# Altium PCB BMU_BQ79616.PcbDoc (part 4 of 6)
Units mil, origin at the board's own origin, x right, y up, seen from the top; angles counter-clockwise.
Board outline 7605 x 4005 mil, 4 copper layers (Top Layer, Layer 1, Layer 2, Bottom Layer), stack 37.446 mil thick; 709 components, 447 nets, 2028 pads, 1862 vias.
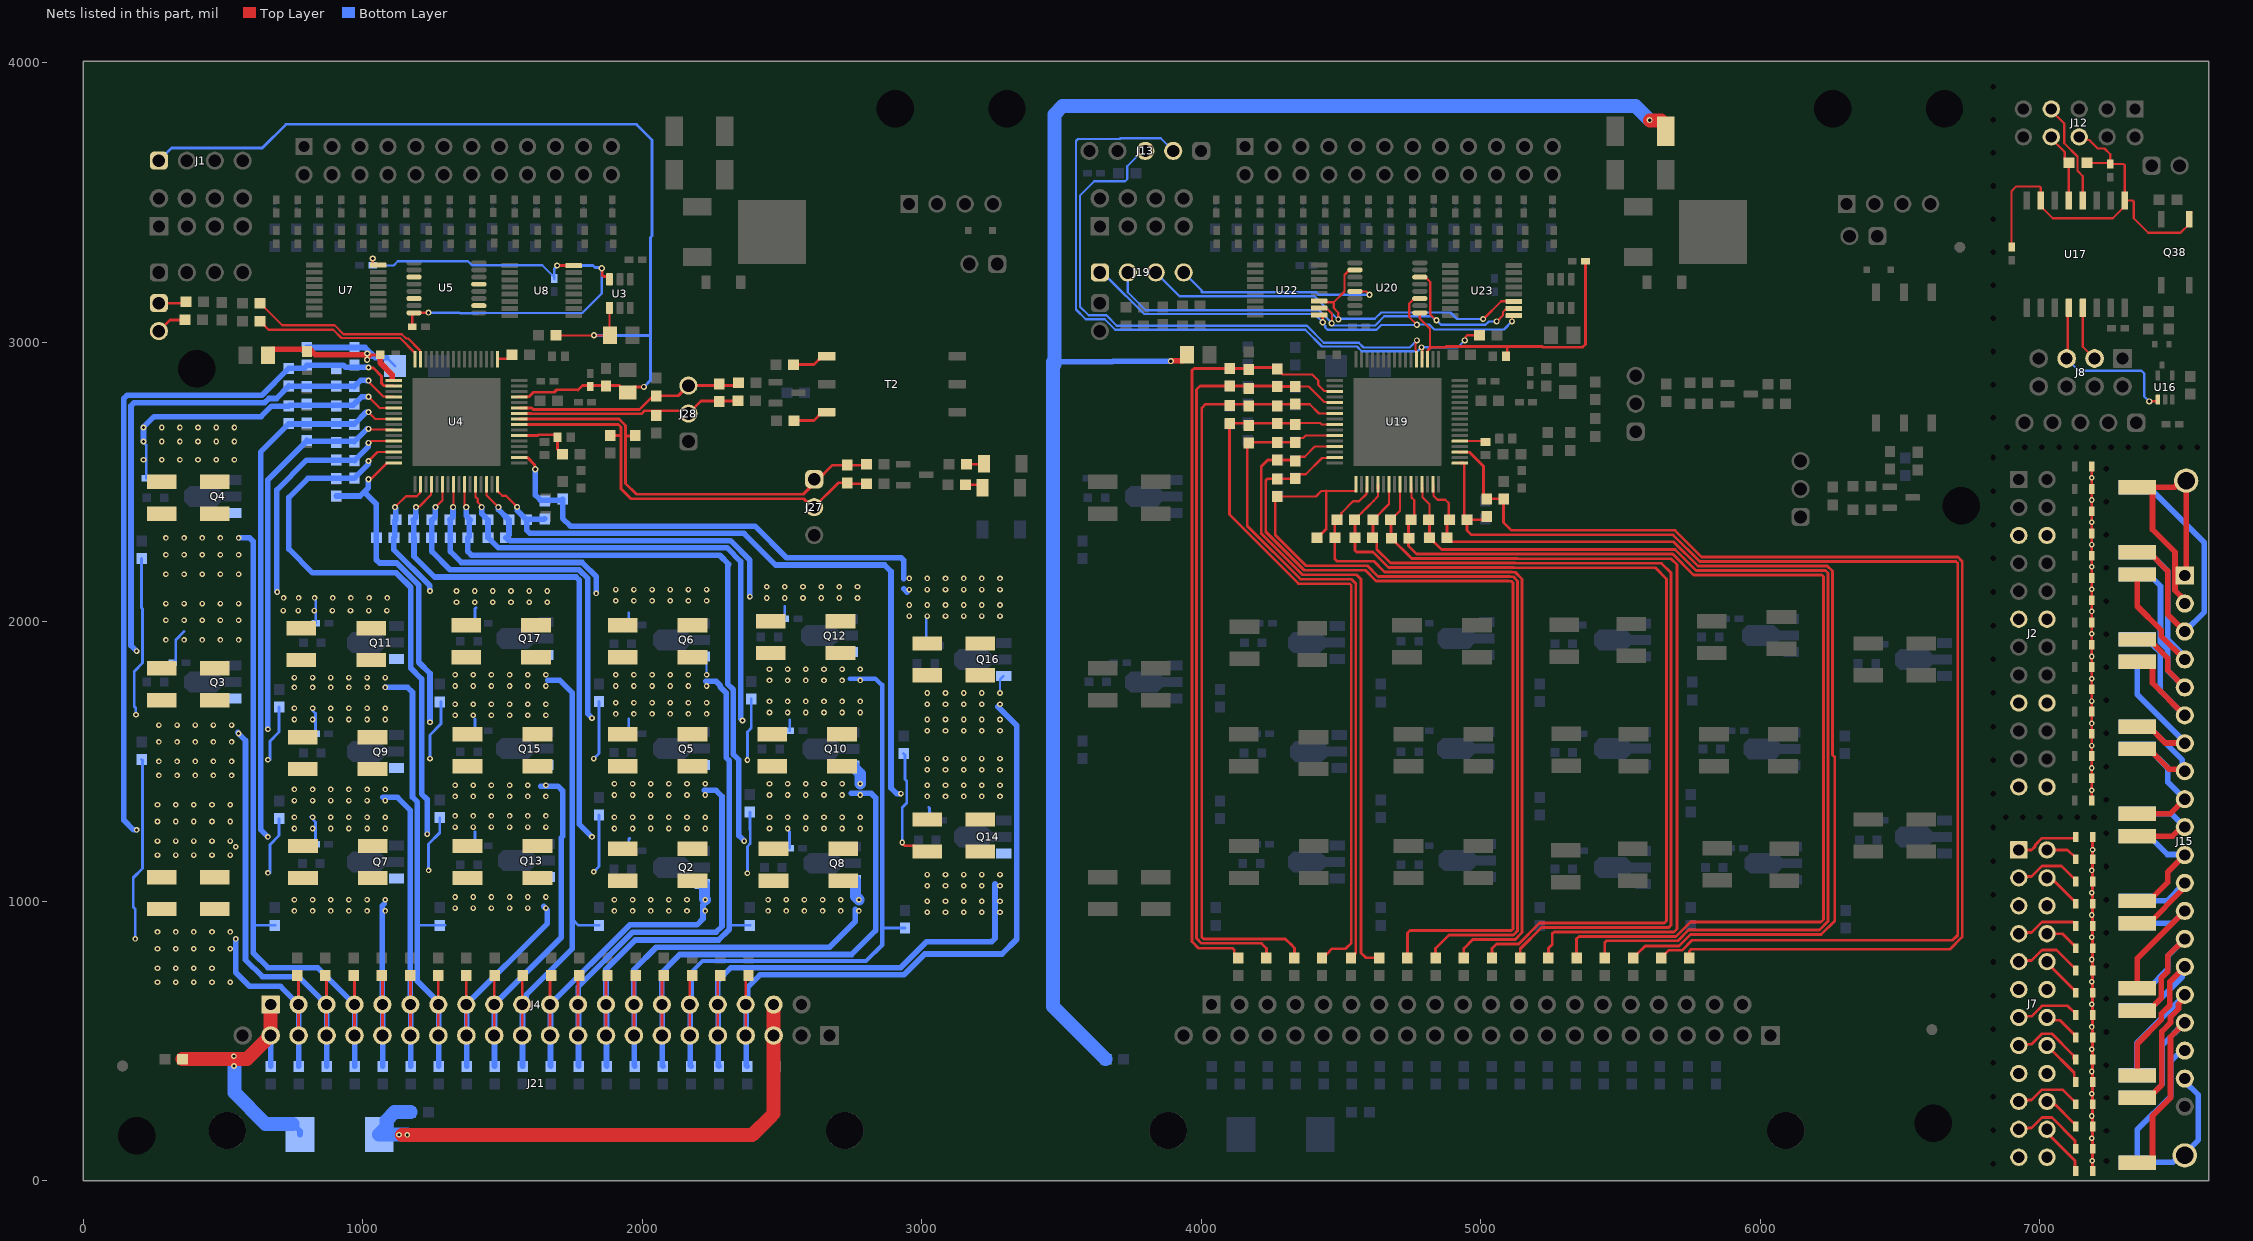
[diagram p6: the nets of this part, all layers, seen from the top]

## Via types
v1: diameter 20, hole 10, Top Layer to Bottom Layer, tented both sides, 1385 vias
v2: diameter 22.01, hole 12.01, Top Layer to Bottom Layer, tented both sides, 405 vias
v3: diameter 19.68, hole 7.87, Top Layer to Bottom Layer, 72 vias

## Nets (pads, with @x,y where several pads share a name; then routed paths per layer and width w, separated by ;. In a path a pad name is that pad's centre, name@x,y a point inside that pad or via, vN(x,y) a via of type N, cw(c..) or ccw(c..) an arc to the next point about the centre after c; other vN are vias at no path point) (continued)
A1_PWR: R152.2 R156.1 R417.1 | length 6223.9
  Top Layer w20: v2(3891.43,2932.62) 3891.97,2932.62 3892.85,2933.5 3935,2933.5 3950,2948.5 R156.1@3950,2955
  Top Layer w30: v2(5605,3795) v2@5606.85,3793.15 ; R152.2@5646.42,3793.15 5662.91,3776.65 R152.2@5662.91,3755 R152.2@5662.91,3745
  Top Layer w50: v2@5606.85,3793.15 R152.2@5646.42,3793.15
  Bottom Layer w20: 3470,2930 3475,2930 3681.63,2930 3684.26,2932.62 v2(3891.43,2932.62)
  Bottom Layer w30: R417.1@3658.39,435 R417.1@3659.37,435
  Bottom Layer w50: 3470,2930 3470,623.39 R417.1@3658.39,435 ; 3475,2920 3475,2930 3475,3815.71 3504.29,3845 5555,3845 v2(5605,3795)
A1_REFHP: C165.2 U19.37 | length 92.5
  Top Layer w8: U19.37@4926.18,2646.69 5014.29,2646.69 C165.2@5017.36,2643.62
A1_RHS_T_MUX: J19.4 U20.13 | length 758.8
  Top Layer w8: U20.13@4550.22,3182.2 4589.78,3182.2 4601.98,3170 v2(4602.36,3170)
  Bottom Layer w8: J19.4@3937.36,3250 4002.36,3185 4002.36,3179 4411.7,3179 4420.7,3170 v2(4602.36,3170)
A1_RX: J13.2 R143.2 U19.52 | length 2542.7
  Top Layer w8: U19.52@4790.35,2940 4792.26,2941.91 v2@4792.26,2973.9 ; v2(4943.42,3006.91) 4946.1,3009.59 4946.1,3018.94 4952.16,3025 R143.2@4995.87,3025
  Bottom Layer w8: 3710,3727.48 3559.06,3727.48 3551.9,3720.31 3551.9,3117.3 3586.72,3082.48 3654.96,3082.48 3692.44,3045 4372.48,3045 4432.73,2984.75 4557.82,2984.75 4575.01,2967.56 4774.07,2967.56 v2(4788.42,2981.91) 4918.42,2981.91 v2(4943.42,3006.91) ; 3710,3730 3855,3730 J13.2@3900,3685
A1_RX_CO: J8.3 U17.13 | length 199.1
  Top Layer w8: U17.13@7154.95,3123.57 7154.95,2984.26 J8.3@7197.24,2941.97
A1_THER_A0: J19.3 U20.10 U22.11 U23.11 | length 1653.4
  Top Layer w8: U22.11@4445.71,3148.23 4450.57,3143.37 4474.05,3143.37 ; v2(4490.9,3082.01) 4490.9,3106.16 4474.05,3123.01 4474.05,3143.37 ; U20.10@4546.22,3258.98 4530.44,3258.98 4512.66,3241.2 4512.66,3181.98 4474.05,3143.37 ; v2(5008.82,3083.5) 5010.57,3083.5 5073.68,3146.61 U23.11@5121.54,3146.61
  Bottom Layer w8: J19.3@3837.36,3250 3922.36,3165 4405.9,3165 4488.9,3082.01 v2(4490.9,3082.01) 4492.73,3083.84 4620.93,3083.84 4644.09,3107 4892.1,3107 4915.6,3083.5 v2(5008.82,3083.5)
A1_THER_A1: J19.2 U20.6 U22.10 U23.10 | length 1816.9
  Top Layer w8: U22.10@4445.71,3119.31 4447.24,3117.78 4452.36,3117.78 4467.76,3102.39 4467.76,3069.11 v2(4466.65,3068) ; U20.6@4782.5,3233.39 4802.28,3233.39 4820.06,3215.61 4820.06,3099.78 4841.08,3078.77 v2(4841.88,3078.77) ; v2(5057.36,3074.8) 5058.46,3074.8 5079.65,3095.98 5079.65,3107.29 5088.52,3116.17 5116.68,3116.17 U23.10@5121.54,3121.02
  Bottom Layer w8: J19.2@3737.36,3250 3737.36,3179.4 3801.76,3115 4421.28,3115 4466.65,3069.63 v2(4466.65,3068) ; v2@4464.95,3063.2 4467.76,3060.39 4622.76,3060.39 4655.36,3093 4823.85,3093 4838.08,3078.77 v2(4841.88,3078.77) 4858.14,3062.5 5017.52,3062.5 5029.82,3074.8 v2(5057.36,3074.8)
A1_THER_A2: J19.1 U20.3 U22.9 U23.9 | length 1775.9
  Top Layer w8: U22.9@4431.05,3092.19 4434.81,3092.19 v2(4434.81,3071.77) ; v2(4772.02,3063.01) 4744.94,3090.05 4744.94,3138.84 4762.72,3156.61 U20.3@4782.5,3156.61 ; v2(5112.36,3075) 5112.36,3090.57 5117.22,3095.43 U23.9@5121.54,3095.43
  Bottom Layer w8: J19.1@3637.36,3250 3643.99,3250 3667.4,3226.59 3670.37,3226.59 3795.96,3101 4405.58,3101 v2(4434.81,3071.77) 4434.81,3067.98 4443.75,3059.03 4443.75,3052.92 4451.67,3045 4627.32,3045 4644.59,3062.27 4771.29,3062.27 v2(4772.02,3063.01) ; v2(4772.02,3063.01) 4772.94,3063.91 4816.09,3063.91 4834,3046 5083.37,3046 v2(5112.36,3075)
A1_TSREF: C158.1 R195.1 U19.51 U20.1 | length 1081.7
  Top Layer w8: U20.1@4782.5,3105.43 4782.5,3084.94 4819,3048.45 4819,2981.93 4820.4,2980.53
  Top Layer w10: U19.51@4810.04,2940 4810.94,2940.91 4810.94,2971.07 4820.4,2980.53 ; 4819.02,2981.91 4873.83,2981.91 4876.62,2984.7 5095,2984.7 5220.61,2984.7 5222.81,2982.5 5365.16,2982.5 5374.86,2992.2 5374.86,3289.86 R195.1@5375,3290 ; C158.1@5090.98,2950 5095,2954.02 5095,2984.86
A1_TX: J13.3 U19.53 | length 2071.8
  Top Layer w8: U19.53@4770.67,2940 4768.76,2941.91 4768.76,2971.86 4767.42,2973.21 4767.42,2998.63 4772,3003.21 v2(4772,3007)
  Bottom Layer w8: J13.3@3800,3685 3790.16,3685 3735,3629.84 3735,3583.97 3727.33,3576.3 3617.39,3576.3 3565.9,3524.8 3565.9,3127.79 3597.21,3096.48 3660.76,3096.48 3698.24,3059 4378.28,3059 4438.53,2998.75 4563.62,2998.75 4580.81,2981.56 4746.56,2981.56 v2(4772,3007)
A1_TX_CO: J8.5 U16.1 U17.12 | length 627.1
  Top Layer w8: J8.5@7097.24,2941.97 7101.09,2945.82 7101.09,3119.72 U17.12@7104.95,3123.57 ; v2(7392.76,2788.65) 7419.94,2788.65 7423.82,2792.52 U16.1@7423.82,2795
  Bottom Layer w8: J8.5@7097.24,2941.97 7140.7,2898.5 7365.01,2898.5 7375,2888.52 7375,2806.41 v2(7392.76,2788.65)
A1_USB2ANY_3.3V: C4.2 C120.2 J12.6 Q38.1 R147.1 U17.1 U17.7 | length 1549.2
  Top Layer w8: C120.2@6900.24,3340.59 6900.24,3540.97 6917.24,3557.97 6999.95,3557.97 7004.95,3552.97 U17.7@7004.95,3507.43 7004.95,3486.76 7047.74,3443.97 7262.15,3443.97 7304.95,3486.76 U17.1@7304.95,3507.43 ; J12.6@7137.24,3733.97 7147.53,3723.67 7178.09,3723.67 7208.63,3693.13 7233.07,3693.13 7253.24,3672.97 C4.2@7253.24,3638.21 ; R147.1@7169.24,3641.97 7249.48,3641.97 C4.2@7253.24,3638.21 ; Q38.1@7543.76,3464.97 7535.95,3457.16 Q38.1@7535.95,3440.61 7535.95,3422.89 7505.02,3391.97 7389.24,3391.97 7337.24,3443.97 7337.24,3502.74 7332.55,3507.43 U17.1@7304.95,3507.43 ; C4.2@7253.24,3638.21 7300.26,3638.21 7304.95,3633.53 U17.1@7304.95,3507.43
A1_USB2ANY_RX_3.3: J12.8 R147.2 U17.5 | length 254.6
  Top Layer w8: J12.8@7037.24,3733.97 7090.56,3680.65 7090.56,3655.06 7104.95,3640.67 U17.5@7104.95,3507.43
A1_USB2ANY_TX_3.3: J12.7 U17.4 | length 375.3
  Top Layer w8: J12.7@7037.24,3833.97 7088.24,3782.97 7088.24,3712.5 7135.93,3664.81 7135.93,3613.62 7154.95,3594.61 U17.4@7154.95,3507.43
A1_VC0: C219.2 C222.1 R501.2 U19.35 | length 4431
  Top Layer w10: U19.35@4926.18,2607.32 4927.09,2606.42 4960.19,2606.42 5010.28,2556.33 5010.28,2452.09 C219.2@5018.86,2443.5 ; C219.2@5022.36,2440 5080.87,2440 C222.1@5082.36,2438.5 5082.36,2355 5110.36,2327 5695.36,2327 5790.71,2231.65 6689.21,2231.65 6708.13,2231.65 6723.36,2216.42 6723.36,2197.5 6723.36,871.57 6679.6,827.81 5753.22,827.81 5747.36,821.95 R501.2@5747.36,796.5
A1_VC1: C215.2 C219.1 R493.2 U19.33 | length 4562.9
  Top Layer w10: U19.33@4926.18,2567.95 4940.87,2567.95 4941.77,2567.05 C215.2@4941.77,2365 ; C219.1@5022.36,2377.01 5010.35,2365 C215.2@4951.77,2365 4951.77,2326.59 4967.36,2311 5688.73,2311 5784.09,2215.65 6701.5,2215.65 6707.36,2209.79 6707.36,878.2 6689.17,860 5756.92,860 5720.92,824 5672.94,824 5646.42,797.48 R493.2@5646.42,796.5
A1_VC2: C211.2 C215.1 R483.2 U19.31 | length 3697.1
  Top Layer w8: U19.31@4829.72,2491.18 4831.63,2489.28 4831.63,2450.53 4845.34,2436.82 4873.31,2436.82 4885.54,2424.59 4885.54,2368.24 C215.1@4888.78,2365
  Top Layer w10: C215.1@4888.78,2365 4879.76,2355.98 C211.2@4879.76,2300 4893.46,2286.3 5690.81,2286.3 5777.46,2199.65 6225.99,2199.65 6240.69,2199.65 6259.44,2180.9 6259.44,1523.23 6267.36,1515.3 6267.36,929.25 6218.77,880.66 5750.91,880.66 5710.24,840 5588.99,840 5560.17,811.18 5559.19,811.18 5557.36,809.36 5557.36,808.37 R483.2@5545.49,796.5
A1_VC3: C207.2 C211.1 R473.2 U19.29 | length 3806.5
  Top Layer w8: U19.29@4790.35,2491.18 U19.29@4792.26,2489.28 ; U19.29@4792.26,2479.28 4792.26,2445.1 4817.36,2420 4817.36,2369.09 C207.2@4813.27,2365
  Top Layer w10: C207.2@4813.27,2365 4816.77,2361.5 C211.1@4816.77,2300 4817.76,2300 4859.5,2258.25 5696.23,2258.25 5770.83,2183.65 6234.07,2183.65 6243.44,2174.27 6243.44,927.96 6212.15,896.66 5744.28,896.66 5705.62,858 5450.41,858 5444.55,852.14 R473.2@5444.55,796.5
A1_VC4: C203.2 C207.1 R463.2 U19.27 | length 3963.1
  Top Layer w8: C207.1@4750.28,2365 4762.36,2377.09 4762.36,2435 4752.89,2444.47 U19.27@4752.89,2479.28 ; U19.27@4750.98,2491.18 U19.27@4752.89,2489.28
  Top Layer w10: C207.1@4750.28,2365 4741.77,2356.5 4741.77,2270.59 4770.11,2242.25 5687.74,2242.25 5762.34,2167.65 6221.58,2167.65 6227.44,2161.79 6227.44,934.58 6218.65,925.8 5750.79,925.8 5698.99,874 5352.36,874 5343.61,865.25 R463.2@5343.61,796.5
A1_VC5: C198.2 C203.1 R453.2 U19.25 | length 3108.6
  Top Layer w8: C198.2@4679.25,2365 4711.61,2397.36 U19.25@4711.61,2481.18
  Top Layer w10: C198.2@4679.25,2365 4679.25,2300.47 4678.78,2300 4679.76,2300 4753.51,2226.25 5131.71,2226.25 5132.97,2225 5682.36,2225 5702.36,2205 5702.36,900 5692.36,890 5262.23,890 5256.38,884.14 5256.38,845.2 5242.67,831.5 R453.2@5242.67,796.5
A1_VC6: C196.2 C198.1 R443.2 U19.23 | length 3731.9
  Top Layer w8: C198.1@4615.28,2365 4616.26,2365 4672.24,2420.98 U19.23@4672.24,2481.18
  Top Layer w10: C198.1@4615.28,2365 4615.28,2302.01 C196.2@4613.27,2300 4614.35,2298.92 4615.33,2298.92 4627.95,2286.3 4627.95,2259.41 4677.11,2210.25 5125.08,2210.25 5126.34,2209 ; R443.2@5141.74,796.5 5141.74,829.87 5217.87,906 5673.36,906 5681.36,914 5681.36,1552.76 5681.36,2175.14 5647.5,2209 ; 5126.34,2209 5647.5,2209 ; 5126.34,2209 5647.5,2209
A1_VC7: C192.2 C196.1 R433.2 U19.21 | length 3353
  Top Layer w8: C192.2@4548.27,2365 4562.97,2379.7 4564.18,2379.7 4577.36,2392.88 4577.36,2393.11 4594.86,2410.61 4617.31,2433.06 4632.87,2448.62 U19.21@4632.87,2474.9
  Top Layer w10: C192.2@4548.27,2365 4550.28,2362.99 C196.1@4550.28,2300 4550.28,2255.86 4556.13,2250 4614.73,2250 4670.48,2194.25 5118.46,2194.25 5119.71,2193 5625.58,2193 5665.36,2153.21 5665.36,1546.13 5665.36,929.84 5657.52,922 5211.24,922 5136.24,847 5056.62,847 5040.8,831.18 R433.2@5040.8,796.5 ; U19.21@4632.87,2474.9 U19.21@4632.87,2491.18
A1_VC8: C192.1 C221.2 R423.2 U19.19 | length 2549.1
  Top Layer w8: C192.1@4485.28,2365 4486.26,2365 4500.96,2379.7 4500.96,2388.3 4543.66,2431 4565.12,2431 4591.6,2457.48 U19.19@4591.6,2479.28 ; U19.19@4591.6,2489.28 U19.19@4593.5,2491.18
  Top Layer w10: C192.1@4485.28,2365 4478.27,2357.99 C221.2@4478.27,2300 4478.27,2224.09 4486.11,2216.25 4618.48,2216.25 4656.48,2178.25 5111.83,2178.25 5113.08,2177 5123.76,2177 5148.36,2152.4 5148.36,887.6 5123.76,863 4971.68,863 4939.86,831.18 R423.2@4939.86,796.5
A1_VC9: C217.2 C221.1 R494.2 U19.17 | length 3176.4
  Top Layer w8: C217.2@4271.77,2448.5 4410.78,2448.5 4429.87,2467.6 4447.36,2467.6 4552.23,2467.6 4554.13,2469.51 U19.17@4554.13,2491.18
  Top Layer w10: C217.2@4271.77,2448.5 4265,2441.73 4265,2310.51 4375.26,2200.25 4594.74,2200.25 4632.74,2162.25 5105.2,2162.25 5106.46,2161 5117.13,2161 5132.36,2145.77 5132.36,894.23 5117.13,879 4886.74,879 4838.92,831.18 R494.2@4838.92,796.5 ; C221.1@4415.28,2300 4416.26,2300 4429.96,2313.7 4429.96,2314.69 4447.36,2332.09 4447.36,2467.6
A1_VC10: C213.2 C217.1 R484.2 U19.15 | length 3137.6
  Top Layer w8: C213.2@4336.77,2512.01 4336.77,2512.99 4351.47,2527.69 4374.32,2527.69 4432.36,2585.73 4475.46,2585.73 U19.15@4477.36,2587.64
  Top Layer w10: C213.2@4336.77,2511.5 C217.1@4271.77,2511.5 4236.86,2511.5 4231,2505.64 4231,2321.88 4368.63,2184.25 4588.11,2184.25 4626.11,2146.25 5098.58,2146.25 5099.83,2145 5110.5,2145 5116.36,2139.14 5116.36,900.86 5110.5,895 4747.36,895 4737.99,885.62 R484.2@4737.99,796.5
A1_VC11: C209.2 C213.1 R474.2 U19.13 | length 2370.7
  Top Layer w8: C213.1@4336.77,2575.98 4351.47,2590.69 4370.36,2590.69 4406.68,2627.01 U19.13@4462.36,2627.01
  Top Layer w10: C213.1@4336.77,2575.98 C213.1@4336.77,2575 4333.27,2578.5 C209.2@4271.77,2578.5 4238.07,2578.5 4215,2555.43 4215,2315.25 4362,2168.25 4556.25,2168.25 4572.36,2152.14 4572.36,815 4589.88,797.48 4637.05,797.48 R474.2@4637.05,796.5 ; U19.13@4462.36,2627.01 U19.13@4477.36,2627.01
A1_VC12: C205.2 C209.1 R10.2 R464.2 U19.11 | length 2448.9
  Top Layer w8: C205.2@4336.77,2642.01 4336.77,2642.99 4351.47,2657.69 4365.06,2657.69 4373.74,2666.38 U19.11@4477.36,2666.38
  Top Layer w10: C205.2@4336.77,2642.01 4271.77,2642.01 4171.77,2642.01 4166.77,2647.01 4165,2645.24 4165,2342.63 4355.37,2152.25 4536.88,2152.25 4553.36,2135.77 4553.36,814.73 4536.11,797.48 R464.2@4536.11,796.5
A1_VC13: C200.2 C205.1 R10.1 R11.2 R454.2 U19.9 | length 2667.5
  Top Layer w8: C205.1@4336.77,2705 4341.77,2710 4342.78,2711 4352.36,2711 4426.36,2711 4431.61,2705.75 U19.9@4477.36,2705.75
  Top Layer w10: C205.1@4352.36,2710 4341.77,2710 4336.77,2710 4271.77,2710 4166.77,2710 R11.2@4101.77,2710 4101.77,2383.23 4348.75,2136.25 4530.25,2136.25 4537.36,2129.14 4537.36,898.68 4537.36,850 4517.36,830 4468.68,830 4449.86,811.18 4448.88,811.18 4435.17,797.48 R454.2@4435.17,796.5
A1_VC14: C197.2 C200.1 R11.1 R79.2 R444.2 U19.7 | length 2782.2
  Top Layer w8: C197.2@4336.77,2778.5 4388.56,2778.5 4421.95,2745.12 U19.7@4477.36,2745.12
  Top Layer w10: C200.1@4271.77,2771.5 C200.1@4278.78,2778.5 ; R444.2@4334.24,796.5 4334.24,832.48 4320.54,846.18 4319.55,846.18 4300.73,865 4008.22,865 4002.36,870.86 4002.36,2765 4015.87,2778.5 4101.77,2778.5 4166.77,2778.5 C200.1@4278.78,2778.5 ; C197.2@4336.77,2778.5 C200.1@4278.78,2778.5
A1_VC15: C193.2 C197.1 R79.1 R84.2 R434.2 U19.5 | length 2786.9
  Top Layer w8: C197.1@4336.77,2841.5 4385.06,2841.5 4440.16,2786.39 4475.46,2786.39 U19.5@4477.36,2784.49
  Top Layer w10: R434.2@4233.3,796.5 4233.3,831.18 4215.48,849 4001.59,849 3983.36,867.23 3983.36,2831 3995.87,2843.5 R84.2@4101.77,2843.5 4270.28,2843.5 C193.2@4271.77,2842.01 4272.28,2841.5 C197.1@4336.77,2841.5
A1_VC16: C193.1 R84.1 R179.2 R424.2 U19.3 | length 2802.9
  Top Layer w8: C193.1@4271.77,2905 4271.77,2904.02 4286.47,2889.31 4287.46,2889.31 4291.77,2885 4397.36,2885 4418.87,2863.49 4418.87,2847.28 4440.39,2825.76 4475.46,2825.76 U19.3@4477.36,2823.86
  Top Layer w10: R424.2@4132.36,796.5 4118.66,810.2 4118.66,825.2 4112.36,831.5 3990.87,831.5 3967.36,855 3967.36,2900 3973.86,2906.5 R84.1@4101.77,2906.5 4163.86,2906.5 4167.36,2910 4266.77,2910 C193.1@4271.77,2905
A1M_CELL0S: J2.5 J2.6 J2.11 J2.12 J2.17 J2.18 J2.23 J2.24 J7.5 J7.6 J7.11 J7.12 J7.17 J7.18 J7.23 J7.24 J15.18 J15.19 R242.1 RT1.2 RT2.1 RT3.2 RT4.1 RT5.2 RT6.1 RT7.2 RT8.1 RT9.2 RT10.1 RT11.2 RT12.1 RT13.2 RT14.1 RT15.2 RT16.1 RT17.2 RT18.1 RT19.2 RT20.1 RT21.2 RT22.1 RT23.2 RT24.1 RT25.2 RT26.1 RT27.2 RT28.1 RT29.2 RT30.1 RT31.2 RT32.1 TP2.1 | length 3399.2
  Top Layer w10: RT16.1@7186.81,1360 RT15.2@7186.81,1439.67 RT14.1@7186.81,1519.33 RT13.2@7186.81,1599 RT12.1@7186.81,1678.67 RT11.2@7186.81,1758.33 RT10.1@7186.81,1838 RT9.2@7186.81,1917.67 RT8.1@7186.81,1997.33 RT7.2@7186.81,2077 RT6.1@7186.81,2156.67 RT5.2@7186.81,2236.33 RT4.1@7186.81,2316 RT3.2@7186.81,2395.67 RT2.1@7186.81,2475.33 RT1.2@7186.81,2555 ; RT32.1@7190,34.53 7189.5,35.04 7189.5,70.69 v1(7189,71.19) 7189.5,71.69 7189.5,113.7 RT31.2@7190,114.2 7190,151.19 RT30.1@7190,193.87 RT29.2@7190,273.53 RT28.1@7190,353.2 RT27.2@7190,432.87 RT26.1@7190,512.53 RT25.2@7190,592.2 RT24.1@7190,671.87 RT23.2@7190,751.53 RT22.1@7190,831.2 RT21.2@7190,910.87 RT20.1@7190,990.53 RT19.2@7190,1070.2 7190,1110.03 RT18.1@7190,1149.87 7190,1155 v1(7190,1184.04) ; RT18.1@7190,1150 v1(7190,1184.04) ; RT17.2@7190,1229.53 v1(7190,1184.04)
  Bottom Layer w20: J15.19@7520,365 7520,355 7568.48,306.52 7568.48,145.46 7520,96.98 TP2.1@7520,90 7501.87,90 7476.87,65 R242.1@7350,65 7350,182.14 7470,302.14 7470,429.28 7472.12,429.28 7507.83,465 J15.18@7520,465
  other v1: 7187.33,151.19 7187.33,231.19 7187.33,310.48 7187.33,390.48 7187.33,470.15 7187.33,550.15 7187.33,631.41 7187.33,711.41 7187.33,791.08 7187.33,871.08 7187.33,950.37 7187.33,1030.37 7187.33,1110.03 7187.33,1396.99 7187.33,1476.66 7187.33,1556.66 7187.33,1635.95 7187.33,1715.95 7187.33,1795.61 7187.33,1875.61 7187.33,1956.88 7187.33,2036.88 7187.33,2116.54 7187.33,2196.54 7187.33,2275.83 7187.33,2355.83 7187.33,2435.5 7187.33,2515.5
A1M_CELL1: J15.17 R240.1 R242.2 | length 958.1
  Top Layer w20: R240.1@7350,63.86 7391.34,63.86 7404.43,76.95 7404.43,231.89 7469.02,296.48 7469.02,514.02 J15.17@7520,565
  Bottom Layer w20: R242.2@7350,297.28 7391.34,297.28 7440,345.94 7440,485 J15.17@7520,565
A1M_CELL2: J15.16 R238.1 R240.2 | length 823.9
  Top Layer w20: R240.2@7350,296.14 7391.34,296.14 7438.02,342.82 7438.02,533.78 7469.02,564.78 7469.02,586.12 7497.43,614.53 7497.43,631.62 7520,654.19 J15.16@7520,665
  Bottom Layer w20: R238.1@7350,376.98 7347.57,379.41 7347.57,491.69 7520,664.12 J15.16@7520,665
A1M_CELL3: J15.15 R236.1 R238.2 | length 709.8
  Top Layer w20: R236.1@7350,376 7350,489.6 7435.43,575.03 7435.43,596.37 7466.43,627.37 7466.43,711.43 J15.15@7520,765
  Bottom Layer w20: R238.2@7350,609.26 7391.34,609.26 7511.4,729.32 7511.4,756.4 J15.15@7520,765
A1M_CELL4: J15.14 R234.1 R236.2 | length 622
  Top Layer w20: R236.2@7350,608.28 7391.34,608.28 7435.43,652.38 7435.43,724.27 7458.39,747.23 7458.39,803.39 J15.14@7520,865
  Bottom Layer w20: R234.1@7350,688.96 7391.34,688.96 7459.16,756.78 7459.16,804.16 J15.14@7520,865
A1M_CELL5: J15.13 R232.1 R234.2 | length 535.4
  Top Layer w20: R232.1@7350,688.14 7350,795 J15.13@7520,965
  Bottom Layer w20: R234.2@7350,921.24 7475.4,921.24 7519.15,965 J15.13@7520,965
A1M_CELL6: J15.12 R230.1 R232.2 | length 435.7
  Top Layer w20: R232.2@7350,920.43 7391.34,920.43 7512.35,1041.44 7512.35,1057.35 J15.12@7520,1065
  Bottom Layer w20: R230.1@7350,1000.94 7455.94,1000.94 J15.12@7520,1065
A1M_CELL7: J15.11 R226.1 R230.2 | length 457.6
  Top Layer w20: R226.1@7350,1000.29 7391.34,1000.29 7458.39,1067.34 7458.39,1103.39 J15.11@7520,1165
  Bottom Layer w20: R230.2@7350,1233.22 7391.34,1233.22 7457.52,1167.04 7517.96,1167.04 J15.11@7520,1165
A1M_CELL8: J15.10 R222.1 R226.2 | length 373.3
  Top Layer w20: R226.2@7350,1232.57 7476.76,1232.57 7509.19,1265 J15.10@7520,1265
  Bottom Layer w20: R222.1@7350,1312.92 7472.08,1312.92 J15.10@7520,1265
A1M_CELL9: J15.9 R219.1 R222.2 | length 466.6
  Top Layer w20: R219.1@7350,1312.43 7467.43,1312.43 J15.9@7520,1365
  Bottom Layer w20: R222.2@7350,1545.2 7391.34,1545.2 7459.16,1477.38 7459.16,1425.84 J15.9@7520,1365
A1M_CELL10: J15.8 R217.1 R219.2 | length 457.5
  Top Layer w20: R219.2@7350,1544.71 7391.34,1544.71 7463.41,1472.65 7512.35,1472.65 J15.8@7520,1465
  Bottom Layer w20: R217.1@7350,1624.9 7391.34,1624.9 7511.4,1504.84 7511.4,1473.6 J15.8@7520,1465
A1M_CELL11: J15.7 R215.1 R217.2 | length 557.3
  Top Layer w20: R215.1@7350,1624.57 7391.34,1624.57 7450.02,1565.89 7519.11,1565.89 J15.7@7520,1565
  Bottom Layer w20: R217.2@7350,1857.18 7350,1740.05 7520,1570.05 J15.7@7520,1565
A1M_CELL12: J15.6 R211.1 R215.2 | length 653
  Top Layer w20: R215.2@7350,1856.86 7391.34,1856.86 7404.43,1843.77 7404.43,1780.57 J15.6@7520,1665
  Bottom Layer w20: R211.1@7350,1936.88 7391.34,1936.88 7406.93,1921.29 7406.93,1915.4 7432.93,1889.4 7432.93,1752.07 J15.6@7520,1665
A1M_CELL13: J15.5 R207.1 R211.2 | length 765.1
  Top Layer w20: R207.1@7350,1936.72 7391.34,1936.72 7458.39,1869.66 7458.39,1826.61 J15.5@7520,1765
  Bottom Layer w20: R211.2@7350,2169.16 7391.34,2169.16 7433.16,2127.34 7433.16,1925.94 7459.16,1899.94 7459.16,1825.84 J15.5@7520,1765
A1M_CELL14: J15.4 R205.1 R207.2 | length 852.9
  Top Layer w20: R207.2@7350,2169 7350,2055.4 7435.43,1969.97 7435.43,1949.57 J15.4@7520,1865
  Bottom Layer w20: R205.1@7350,2248.86 7391.34,2248.86 7459.16,2181.03 7459.16,1936.7 7520,1875.87 J15.4@7520,1865
A1M_CELL15: J15.3 R203.1 R205.2 | length 1047.3
  Top Layer w20: R203.1@7350,2248.86 7391.34,2248.86 7458.39,2181.8 7458.39,2026.61 J15.3@7520,1965
  Bottom Layer w20: R205.2@7350,2481.14 7391.34,2481.14 7590,2282.48 7590,2035 J15.3@7520,1965
A1M_CELL16S: J15.1 J15.2 R203.2 TP1.1 | length 996.4
  Top Layer w20: R203.2@7350,2481.14 R203.2@7391.34,2481.14 ; J15.2@7520,2065 7520,2077.17 7485,2112.17 7485,2249.15 7404.43,2329.72 7404.43,2468.05 R203.2@7391.34,2481.14 ; J15.1@7520,2165 7525,2170 TP1.1@7525,2505 7506.87,2505 7483.01,2481.14 R203.2@7391.34,2481.14
A1N_NTC0_C: J7.1 RT17.1 | length 222.4
  Top Layer w10: J7.1@6926.02,1183.49 6971.92,1183.49 6984.9,1196.47 6984.9,1200.85 7009.45,1225.4 7122.67,1225.4 RT17.1@7126.81,1229.53
A1N_NTC1_C: J7.2 RT18.2 | length 118.3
  Top Layer w10: J7.2@7026.81,1183.49 7100.68,1183.49 7126.81,1157.37 RT18.2@7126.81,1149.87
A1N_NTC2_C: J7.3 RT19.1 | length 245.4
  Top Layer w10: J7.3@6926.02,1083.49 6930.4,1087.87 6971.92,1087.87 7009.45,1125.4 7079.11,1125.4 7126.81,1077.7 RT19.1@7126.81,1070.2
A1N_NTC3_C: J7.4 RT20.2 | length 144.8
  Top Layer w10: J7.4@7026.81,1083.49 7040.83,1083.49 7056.01,1068.3 7056.54,1068.3 7121.81,1003.03 7125,1003.03 7126.81,1001.23 RT20.2@7126.81,990.53
A1N_NTC4_C: J7.7 RT21.1 | length 228.6
  Top Layer w10: J7.7@6926.02,883.49 6930.4,887.87 6971.92,887.87 7009.45,925.4 7119.78,925.4 7126.81,918.37 RT21.1@7126.81,910.87
A1N_NTC5_C: J7.8 RT22.2 | length 126.1
  Top Layer w10: J7.8@7026.81,883.49 7082.02,883.49 7126.81,838.7 RT22.2@7126.81,831.2
A1N_NTC6_C: J7.9 RT23.1 | length 253.1
  Top Layer w10: J7.9@6926.02,783.49 6930.4,787.87 6971.92,787.87 7009.45,825.4 7060.44,825.4 7126.81,759.03 RT23.1@7126.81,751.53
A1N_NTC7_C: J7.10 RT24.2 | length 153
  Top Layer w10: J7.10@7026.81,783.49 7026.81,779.37 7126.81,679.37 RT24.2@7126.81,671.87
A1N_NTC8_C: J7.13 RT25.1 | length 236.3
  Top Layer w10: J7.13@6926.02,583.49 6930.4,587.87 6971.92,587.87 7009.45,625.4 7101.11,625.4 7126.81,599.7 RT25.1@7126.81,592.2
A1N_NTC9_C: J7.14 RT26.2 | length 133.8
  Top Layer w10: J7.14@7026.81,583.49 7036.17,574.13 7072.71,574.13 7126.81,520.03 RT26.2@7126.81,512.53
A1N_NTC10_C: J7.15 RT27.1 | length 262.3
  Top Layer w10: J7.15@6926.02,483.49 6930.4,487.87 6971.92,487.87 7009.45,525.4 7044.16,525.4 7121.81,447.75 7121.81,437.87 RT27.1@7126.81,432.87
A1N_NTC11_C: J7.16 RT28.2 | length 171.7
  Top Layer w10: J7.16@7026.81,483.49 7124.59,385.7 7124.59,355.41 RT28.2@7126.81,353.2
A1N_NTC12_C: J7.19 RT29.1 | length 244
  Top Layer w10: J7.19@6926.02,283.49 6930.4,287.87 6971.92,287.87 7009.45,325.4 7082.44,325.4 7126.81,281.03 RT29.1@7126.81,273.53
A1N_NTC13_C: J7.20 RT30.2 | length 143.4
  Top Layer w10: J7.20@7026.81,283.49 7040.83,283.49 7054.35,269.97 7058.2,269.97 7121.81,206.37 7125,206.37 7126.81,204.56 RT30.2@7126.81,193.87
A1N_NTC14_C: J7.21 RT31.1 | length 280.9
  Top Layer w10: J7.21@6926.02,183.49 6930.4,187.87 6971.92,187.87 7009.45,225.4 7044.16,225.4 7126.81,142.75 RT31.1@7126.81,114.2
A1N_NTC15_C: J7.22 RT32.2 | length 190.4
  Top Layer w10: J7.22@7026.81,183.49 7026.81,171.14 7126.81,71.14 RT32.2@7126.81,34.53
A2_AVDD: C19.2 R30.2 U4.38 | length 210.4
  Top Layer w10: U4.38@1558.82,2666.38 1625.84,2666.38 1628.85,2669.39 1686.99,2669.39 C19.2@1696.38,2660 1696.38,2616.14 1712.52,2600 R30.2@1713.5,2600
A2_BAT: C13.2 C14.1 D2.1 R14.1 R29.2 R408.1 U4.1 | length 965.1
  Top Layer w10: v2@1020,2945 1022,2945 1026,2949 1032,2955 C14.1@1062,2955 ; U4.1@1105,2864.13 1105.91,2863.23 U4.1@1110,2863.23
  Top Layer w20: R29.2@660,2960 675,2975 800,2975 810,2975 815.2,2969.8 821.69,2963.31 ; R408.1@800,2972.99 800,2972.01 803.5,2968.5 808.7,2963.31 821.69,2963.31 ; v2@1020,2955 1015.66,2955 830,2955 821.69,2963.31 ; C14.1@1062,2955 1062,2926.66 1105,2883.66 U4.1@1105,2869.02
  Bottom Layer w10: v2@1020,2945 1044.37,2945 1085,2945 1085.63,2944.37 D2.1@1115,2915
  Bottom Layer w20: R14.1@799.41,2981.5 C13.2@969.93,2981.5 1007.87,2981.5 1044.37,2945 1045,2944.37 D2.1@1085.63,2944.37
  other v2: 1015.17,2937.59 1015.66,2959.78
A2_BBN: R51.1 U4.63 | length 674.6
  Top Layer w8: R51.1@631.5,3140 632.48,3140 711.48,3061 898.8,3061 930.8,3029 1139.24,3029 1154.24,3014 1161.21,3014 1204.55,2970.65 1204.55,2941.91 U4.63@1206.46,2940
A2_BBN_CELL: J3.1 R50.1 | length 99.1
  Top Layer w8: J3.1@270,3140 362.01,3140 R50.1@367.01,3145
A2_BBP: R47.1 U4.64 | length 625
  Top Layer w8: R47.1@647.83,3059.65 662.48,3045 893.59,3045 923.59,3015 1133.44,3015 1182.92,2965.53 1184.87,2965.53 1186.77,2963.62 U4.64@1186.77,2940
  Top Layer w10: R47.1@631.5,3075 632.48,3075 R47.1@647.83,3059.65
A2_BBP_CELL: J3.2 R46.1 | length 145.4
  Top Layer w8: J3.2@242.9,3030 J3.2@267.9,3055
  Top Layer w10: J3.2@270,3040 310,3080 R46.1@363.5,3080
A2_CB0: C75.2 C79.1 R130.2 R131.2 R138.1 U4.34 | length 1823
  Top Layer w10: U4.34@1558.82,2587.64 1559.72,2586.73 1589.89,2586.73 1614.7,2561.92 1614.7,2547.87 v2(1616.99,2545.57)
  Bottom Layer w10: R138.1@3016.38,1915 v1@3016.38,2016.38
  Bottom Layer w15: R138.1@3016.38,1915 R138.1@3020.32,1915
  Bottom Layer w20: v2(1616.99,2545.57) 1616.99,2453.01 1635,2435 1650,2435 1711.5,2435 C79.1@1715,2438.5 1715,2370 1743,2342 2403,2342 2516,2229 2926,2229 2935,2220 2935,2153.3 ; 2935,2118.3 2947.05,2106.25
  other v1: 2955,2020 3020,2020 3085,2020 3150,2020 3215,2020 3280,2020 2955,2060 3020,2060 3085,2060 3150,2060 3215,2060 3280,2060 2955,2115 3020,2115 3085,2115 3150,2115 3215,2115 3280,2115 2955,2155 3020,2155 3085,2155 3150,2155 3215,2155 3280,2155
A2_CB1: C71.2 C75.1 R122.2 R127.2 R136.1 U4.32 | length 2510.3
  Top Layer w8: U4.32@1482.05,2491.18 1482.05,2467.56 1498.79,2450.82 1511.74,2450.82 v2(1551.99,2410.57)
  Bottom Layer w10: 3025,1335 3027.76,1332.24 R136.1@3027.76,1290
  Bottom Layer w20: v2(1551.99,2410.57) 1552.38,2410.19 1552.38,2397.54 1584.92,2365 C71.2@1585.91,2365 ; C75.1@1650,2368.5 1648.25,2366.75 1587.66,2366.75 C71.2@1585.91,2365 ; v1(2925.36,1385) 2910,1385 2890,1405 2890,2180 2867,2203 2477,2203 2364,2316 1597.62,2316 1585.91,2327.72 C71.2@1585.91,2365
  other v1: 3020,1375 3085,1375 3150,1375 3215,1375 3280,1375 3020,1415 3085,1415 3150,1415 3215,1415 3280,1415 3020,1470 3085,1470 3150,1470 3215,1470 3280,1470 3020,1510 3085,1510 3150,1510 3215,1510 3280,1510
A2_CB2: C67.2 C71.1 R118.2 R121.2 R134.1 U4.30 | length 1305.1
  Top Layer w8: U4.30@1442.68,2491.18 1442.68,2452.32 v2(1485,2410)
  Bottom Layer w10: R134.1@2510,2010 2510,2055
  Bottom Layer w20: v2(1485,2410) 1485.38,2409.62 1485.38,2401.54 1521.93,2365 C71.1@1522.91,2365 1522.91,2311.02 1511.89,2300 C67.2@1510.91,2300 ; C67.2@1520.59,2296.88 1520.59,2291.3 1526.17,2291.3 1527.47,2290 2315,2290 2385,2220 v1(2385,2090)
  other v1: 2445,2085 2510,2085 2575,2085 2640,2085 2705,2085 2770,2085 2445,2125 2510,2125 2575,2125 2640,2125 2705,2125 2770,2125
A2_CB3: C63.2 C67.1 R112.2 R117.2 R123.1 U4.28 | length 1745.8
  Top Layer w8: U4.28@1403.31,2491.18 1403.31,2446.49 1411.01,2438.79 1411.01,2427.78 1425,2413.79 v2(1425,2410)
  Bottom Layer w10: R123.1@2527.76,1610 2527.76,1648.62
  Bottom Layer w20: v2(1425,2410) 1425.38,2409.62 1425.38,2387.02 C63.2@1437.72,2374.69 ; C63.2@1447.4,2365 1447.66,2364.74 1447.66,2300.26 C67.1@1447.91,2300 1448.9,2300 1484.9,2264 2304.23,2264 2352,2216.23 2352,1653 v1(2358.5,1646.5)
  other v1: 2455,1675 2520,1675 2585,1675 2650,1675 2715,1675 2780,1675 2455,1715 2520,1715 2585,1715 2650,1715 2715,1715 2780,1715
A2_CB4: C59.2 C63.1 R104.2 R106.1 R109.2 U4.26 | length 2281.1
  Top Layer w8: U4.26@1363.94,2491.18 1363.94,2419.85 1370,2413.79 v2(1370,2410)
  Bottom Layer w10: R106.1@2526.38,1190 2526.38,1248.62
  Bottom Layer w20: v2(1370,2410) 1370.38,2409.62 1370.38,2379.03 1374.72,2374.69 1374.72,2373.7 1383.43,2365 C63.1@1384.41,2365 1380.16,2360.75 1380.16,2304.25 C59.2@1375.91,2300 1375.91,2251.3 1389.2,2238 2277,2238 2309.75,2205.25 2305,2200.5 2305,1777.55 2326,1756.55 2326,1524.86 2345.5,1505.36 2345.5,1234.5 v1(2365,1215)
  other v1: 2455,1260 2520,1260 2585,1260 2650,1260 2715,1260 2780,1260 2455,1300 2520,1300 2585,1300 2650,1300 2715,1300 2780,1300
A2_CB5: C58.2 C59.1 R20.1 R102.2 R103.2 U4.24 | length 909.9
  Top Layer w8: v2(1323,2410) 1323.78,2410.78 1323.78,2490.4 U4.24@1324.57,2491.18
  Bottom Layer w10: R20.1@1951.38,1988.15 1951.38,2031.38
  Bottom Layer w20: v2(1323,2410) 1322.62,2409.62 1322.62,2376.71 1320.59,2374.69 1320.59,2373.7 1311.89,2365 C58.2@1310.91,2365 1311.91,2364 1311.91,2301 C59.1@1312.91,2300 1312.91,2251.3 1352.21,2212 1784.82,2212 1835,2161.82 v1(1835,2101.25)
  other v1: 1905,2075 1970,2075 2035,2075 2100,2075 2165,2075 2230,2075 1905,2115 1970,2115 2035,2115 2100,2115 2165,2115 2230,2115
A2_CB6: C54.2 C58.1 R17.1 R96.2 R99.2 U4.22 | length 1413.9
  Top Layer w8: v2(1260,2410) 1285.2,2435.2 U4.22@1285.2,2491.18
  Bottom Layer w10: R17.1@1951.38,1598.77 1951.38,1651.38
  Bottom Layer w20: v2(1260,2410) 1259.62,2409.62 1259.62,2376.7 1257.6,2374.69 1257.6,2373.7 1248.9,2365 C58.1@1247.91,2365 1246.91,2364 1246.91,2301 C54.2@1245.91,2300 1245.91,2292.38 1246.98,2291.3 1246.98,2251.3 1312.28,2186 1774.05,2186 1805,2155.05 1805,1670 v1(1820,1655)
  other v1: 1905,1670 1970,1670 2035,1670 2100,1670 2165,1670 2230,1670 1905,1710 1970,1710 2035,1710 2100,1710 2165,1710 2230,1710
A2_CB7: C5.2 C54.1 R12.1 R23.2 R26.2 U4.20 | length 1908
  Top Layer w8: v2(1190,2410) 1192.68,2412.68 1202.68,2412.68 1243.92,2453.92 1243.92,2489.28 U4.20@1245.83,2491.18
  Bottom Layer w10: R12.1@1951.38,1173.77 1951.38,1221.38 1955,1225
  Bottom Layer w20: v2(1190,2410) 1189.62,2409.62 1189.62,2373.7 C5.2@1180.91,2365 1181.91,2364 1181.91,2301 C54.1@1182.91,2300 1182.91,2234.02 1256.93,2160 1763.28,2160 1775,2148.28 1775,1275 v1(1820,1230)
  other v1: 1900,1260 1965,1260 2030,1260 2095,1260 2160,1260 2225,1260 1900,1300 1965,1300 2030,1300 2095,1300 2160,1300 2225,1300
A2_CB8: C5.1 C78.2 R15.2 R19.2 R139.1 U4.18 | length 548.1
  Top Layer w8: v2@1115,2415 1115.42,2414.58 1119.58,2414.58 1154.1,2449.1 1193.13,2449.1 1204.55,2460.53 1204.55,2489.28 U4.18@1206.46,2491.18
  Bottom Layer w10: R139.1@1401.38,1995 1401.38,2046.38 1405,2050
  Bottom Layer w20: v2(1115,2410) 1115,2409.46 1117.91,2406.54 C5.1@1117.91,2365 1114.41,2361.5 1114.41,2303.5 C78.2@1110.91,2300 1110.91,2257.17 1239.15,2128.92 v1@1239.15,2115.85
  other v1: 1335,2070 1400,2070 1465,2070 1530,2070 1595,2070 1660,2070 1240,2110 1335,2110 1400,2110 1465,2110 1530,2110 1595,2110 1660,2110
A2_CB9: C74.2 C78.1 R125.2 R126.2 R137.1 U4.16 | length 1271.8
  Top Layer w8: v2(1020,2510) 1022.68,2512.68 1031.11,2512.68 1086.38,2567.95 U4.16@1110,2567.95
  Bottom Layer w10: R137.1@1401.38,1610 1401.38,1651.38
  Bottom Layer w20: C74.2@904.41,2450 990,2450 1004.81,2464.81 ; v2(1020,2510) 1019.62,2509.62 1019.62,2479.62 1004.81,2464.81 ; v1(1240,1640) 1240,1815 1200,1855 1200,2131.3 1121.3,2210 1059.63,2210 1047.91,2221.72 C78.1@1047.91,2300 1047.91,2421.7 1004.81,2464.81
  other v1: 1330,1665 1395,1665 1460,1665 1525,1665 1590,1665 1655,1665 1330,1705 1395,1705 1460,1705 1525,1705 1590,1705 1655,1705
A2_CB10: C70.2 C74.1 R119.2 R120.2 R135.1 U4.14 | length 2085.4
  Top Layer w8: v2(1020,2575) 1052.32,2607.32 U4.14@1110,2607.32
  Bottom Layer w10: R135.1@1401.38,1198.54 1401.38,1248.62
  Bottom Layer w20: v2(1020,2575) 1019.62,2574.62 1019.62,2564.1 970,2514.49 C70.2@970,2513.5 969.74,2513.25 904.67,2513.25 C74.1@904.41,2512.99 802.99,2512.99 735,2445 735,2260 820,2175 1119.53,2175 1171.25,2123.28 1171.25,1833.75 1210,1795 1210,1383.5 1228.5,1365 1230,1365 v1(1230,1240)
  other v1: 1330,1265 1395,1265 1460,1265 1525,1265 1590,1265 1655,1265 1330,1305 1395,1305 1460,1305 1525,1305 1590,1305 1655,1305
A2_CB11: C66.2 C70.1 R113.2 R116.2 R124.1 U4.12 | length 959.1
  Top Layer w8: v2(1020,2640) 1023.79,2640 1030.48,2646.69 U4.12@1110,2646.69
  Bottom Layer w10: v1@827.05,2086.25 827.05,2083.54 831.38,2079.21 R124.1@831.38,1995
  Bottom Layer w20: v1(693.5,2106.5) 692,2108 692,2472 798.5,2578.5 C66.2@904.41,2578.5 905.41,2577.5 969,2577.5 C70.1@970,2576.5 970,2577.48 1019.62,2627.1 1019.62,2639.62 v2(1020,2640)
  other v1: 715,2040 768.71,2040 825.76,2040 890.76,2040 955.76,2040 1020.76,2040 1085.76,2040 716.29,2085.35 770,2085.35 827.05,2085.35 892.05,2085.35 957.05,2085.35 1022.05,2085.35 1087.05,2085.35
A2_CB12: C62.2 C66.1 R5.2 R105.2 R107.1 R108.2 U4.10 | length 1515.8
  Top Layer w8: v2(1020,2690) 1022.03,2687.97 1108.09,2687.97 U4.10@1110,2686.06
  Bottom Layer w10: v1@820,1685 820,1682.29 830.16,1672.14 R107.1@830.16,1598.76
  Bottom Layer w20: v1(660,1615) 660,2508.11 799.41,2647.52 R5.2@799.41,2648.5 801.91,2646 966.91,2646 C62.2@969.41,2643.5 969.41,2644.49 1014.54,2689.62 1019.62,2689.62 v2(1020,2690)
  other v1: 755,1650 820,1650 885,1650 950,1650 1015,1650 1080,1650 755,1690 820,1690 885,1690 950,1690 1015,1690 1080,1690
A2_CB13: C55.2 C62.1 R1.2 R5.1 R95.1 R100.2 R101.2 U4.8 | length 2041
  Top Layer w8: v2(1020,2750) 1044.57,2725.43 U4.8@1110,2725.43
  Bottom Layer w10: v1@812.05,1301.25 830.16,1283.14 R95.1@830.16,1203.76
  Bottom Layer w20: v1(660,1230) 634,1256 634,2607.11 734.41,2707.52 R1.2@734.41,2708.5 735.41,2707.5 968.41,2707.5 C62.1@969.41,2706.5 969.41,2707.48 1011.54,2749.62 1019.62,2749.62 v2(1020,2750)
  other v1: 755,1260 820,1260 885,1260 950,1260 1015,1260 1080,1260 755,1300 820,1300 885,1300 950,1300 1015,1300 1080,1300
A2_CB14: C7.2 C55.1 R1.1 R6.2 R16.1 R28.2 R67.2 U4.6 | length 1143.9
  Top Layer w8: v2(1020,2805) 1060.2,2764.8 U4.6@1110,2764.8
  Bottom Layer w10: v1(215,2645) 215,2642.29 224.33,2632.97 R16.1@224.33,2513.75
  Bottom Layer w20: v1(215,2645) 215,2696.72 252.39,2734.11 635.56,2734.11 672.95,2771.5 R1.1@734.41,2771.5 737.91,2775 799.41,2775 904.41,2775 965.91,2775 C7.2@969.41,2778.5 969.41,2779.49 978.11,2788.19 979.09,2788.19 995.52,2804.62 1019.62,2804.62 v2(1020,2805)
  other v1: 215,2580 280,2580 345,2580 410,2580 475,2580 540,2580 280,2645 345,2645 410,2645 475,2645 540,2645 215,2695 280,2695 345,2695 410,2695 475,2695 540,2695
A2_CB15: C6.2 C7.1 R2.2 R6.1 R13.1 R22.2 R27.2 U4.4 | length 2024.4
  Top Layer w8: v2(1020,2863) 1022.68,2860.32 1022.68,2856.31 1072.91,2806.08 1108.09,2806.08 U4.4@1110,2804.17
  Bottom Layer w10: R13.1@319.33,1853.75 325,1859.43 328.94,1859.43 330.07,1860.57 330.07,1935.07 360,1965
  Bottom Layer w20: v1(190,1895) 170,1915 170,2772.28 181.72,2784 648.68,2784 663.68,2799 690.89,2799 734.41,2842.52 R2.2@734.41,2843.5 735.41,2842.5 799.41,2842.5 904.41,2842.5 968.41,2842.5 C7.1@969.41,2841.5 969.41,2842.48 978.11,2851.18 979.09,2851.18 992.53,2864.62 1013.11,2864.62 1014.35,2863.38 1019.62,2863.38 v2(1020,2863)
  other v1: 295,1935 360,1935 425,1935 490,1935 555,1935 295,2005 360,2005 425,2005 490,2005 555,2005 295,2065 360,2065 425,2065 490,2065 555,2065
A2_CB16: C6.1 C13.1 R2.1 R14.2 R18.2 R21.2 U4.2 | length 2630.8
  Top Layer w10: v2(1020,2910) 1022.3,2907.7 1037.3,2907.7 1066.51,2878.49 1066.51,2853.49 1075.55,2844.45 1109.09,2844.45 U4.2@1110,2843.54
  Bottom Layer w20: v1(190,1255) 179,1255 144,1290 144,2798.28 155.72,2810 637.91,2810 R2.1@734.41,2906.5 788.39,2906.5 799.41,2917.52 R14.2@799.41,2918.5 930,2918.5 938.5,2910 v2(1020,2910)
  other v1: 265,1165 330,1165 395,1165 460,1165 525,1165 545,1195 265,1215 330,1215 395,1215 460,1215 525,1215 265,1285 330,1285 395,1285 460,1285 525,1285 265,1345 330,1345 395,1345 460,1345 525,1345
A2_CELL0: C82.1 D44.2 J4.19 J21.3 R9.2 | length 2236
  Top Layer w20: 2460,230 2470,240
  Top Layer w50: 1140,163.41 v1(1158.64,163.41) 2393.41,163.41 2460,230 ; 2470,240 J21.3@2470,519.29 J4.19@2470,630
  Bottom Layer w20: J4.19@2470,630 2472.5,627.5 2472.5,411.36 C82.1@2475,408.86
  Bottom Layer w50: v1(1158.64,163.41) 1157.05,165 D44.2@1058.46,165 1084.65,191.18 1084.65,215.74 1113.94,245.03 R9.2@1171.14,245
  other v1: 1129.2,163.8
A2_CELL0S: C83.1 J4.18 J21.4 Q16.3 R130.1 R131.1 R225.1 | length 2456.6
  Top Layer w10: J21.4@2370,519.29 J4.18@2370,630 R225.1@2370,723.5
  Bottom Layer w8: v1(3280,1745) 3280,1793.07 Q16.3@3292.87,1805.94
  Bottom Layer w15: J21.4@2370,519.29 J21.4@2372.36,521.65
  Bottom Layer w20: C83.1@2374.72,408.86 2372.36,411.22 2372.36,521.65 2372.36,627.64 J4.18@2370,630 2377.48,637.48 2377.48,692.48 2421,736 2935.7,736 3010.7,811 3287.21,811 3340,863.79 3340,1628.3 3272.05,1696.25
  other v1: 3020,1610 3085,1610 3150,1610 3215,1610 3280,1610 3020,1650 3085,1650 3150,1650 3215,1650 3280,1650 3020,1705 3085,1705 3150,1705 3215,1705 3280,1705 3020,1745 3085,1745 3150,1745 3215,1745
A2_CELL1: C85.1 J4.17 J21.5 Q14.3 R122.1 R127.1 R209.1 R213.1 | length 2180.8
  Top Layer w10: J21.5@2270,519.29 J4.17@2270,630 R209.1@2270,724.44 ; v1(2930,1210) 2931.91,1208.09 2931.91,1203.1 2935,1203.1 2939.59,1198.5 2974.41,1198.5 R127.1@3000,1172.91
  Bottom Layer w10: v1(2930,1210) 2930,1335 2946.36,1351.36 2946.36,1429.38 2940,1435.74 2940,1523.5 R213.1@2935,1528.5
  Bottom Layer w20: C85.1@2274.44,408.86 2272.22,411.08 2272.22,627.78 J4.17@2270,630 2270,715 2317,762 2924.93,762 3017.93,855 3250.34,855 3262.05,866.72 3262.05,1061.25
  other v1: 3020,960 3085,960 3150,960 3215,960 3280,960 3020,1000 3085,1000 3150,1000 3215,1000 3280,1000 3020,1055 3085,1055 3150,1055 3215,1055 3280,1055 3020,1095 3085,1095 3150,1095 3215,1095 3280,1095
A2_CELL2: C86.1 J4.16 J21.6 Q12.3 R118.1 R121.1 R193.1 R197.1 | length 2412
  Top Layer w10: J21.6@2170,519.29 J4.16@2170,630 R193.1@2170,725.38
  Bottom Layer w10: 2858.5,910.38 2865.38,903.5 R197.1@2940,903.5
  Bottom Layer w15: J21.6@2170,519.29 2172.08,521.37 J21.6@2172.7,521.99 ; J4.16@2177.7,630 2177.7,747.7 2215.5,785.5 2800.5,785.5 2858.5,843.5 2858.5,910.38 2858.5,1775 2855,1775 2833.75,1796.25 2742.05,1796.25
  Bottom Layer w20: J4.16@2170,630 2172.08,627.92 2172.08,521.37 2172.08,410.94 C86.1@2174.17,408.86
  other v1: 2455,1790 2520,1790 2585,1790 2650,1790 2715,1790 2780,1790 2455,1830 2520,1830 2585,1830 2650,1830 2715,1830 2780,1830
A2_CELL3: C88.1 J4.15 J21.7 Q10.3 R112.1 R117.1 R176.1 R180.1 | length 2247.4
  Top Layer w10: J21.7@2070,519.29 J4.15@2070,630 R176.1@2070,726.32
  Bottom Layer w10: v1(2376,1505) 2376,1606 2390,1620 R180.1@2390,1723.5
  Bottom Layer w20: C88.1@2073.89,408.86 2071.94,410.8 2071.94,628.06 J4.15@2070,630 2070,745 2134,809 2749,809 2835,895 2835,1370 2818.75,1386.25 2747.05,1386.25
  Bottom Layer w40: Q10.3@2749.8,1485.94 2755.08,1485.94 2757.36,1483.66 2757.36,1478.39 2780,1455.75 v1(2780,1420)
  other v1: 2455,1380 2520,1380 2585,1380 2650,1380 2715,1380 2780,1380 2455,1420 2520,1420 2585,1420 2650,1420 2715,1420
A2_CELL4: C89.1 J4.14 J21.8 Q8.3 R104.1 R109.1 R160.1 R164.1 | length 1769.2
  Top Layer w10: J21.8@1970,519.29 J4.14@1970,630 R160.1@1970,727.25
  Bottom Layer w10: v1(2376,1100) 2376,1196 2386,1206 2386,1254.56 2385,1255.56 R164.1@2385,1318.5
  Bottom Layer w20: C89.1@1973.61,408.86 1971.81,410.66 1971.81,628.19 J4.14@1970,630 1970,755 2050,835 2670,835 2762.05,927.05 2762.05,971.25
  Bottom Layer w40: Q8.3@2754.8,1076.57 2760.08,1076.57 2762.36,1074.28 2762.36,1017.64 v1(2775,1005)
  other v1: 2450,965 2515,965 2580,965 2645,965 2710,965 2775,965 2450,1005 2515,1005 2580,1005 2645,1005 2710,1005
A2_CELL5: C90.1 J4.13 J21.9 Q6.3 R102.1 R103.1 R144.1 R148.1 | length 2149.5
  Top Layer w10: J21.9@1870,519.29 J4.13@1870,630 R144.1@1870,728.19
  Bottom Layer w8: Q6.3@2214.8,1875.94 2216.28,1875.94 2230,1862.23 v1(2230,1810)
  Bottom Layer w10: 2311,915 2312.5,913.5 R148.1@2385,913.5
  Bottom Layer w20: C90.1@1873.33,408.86 1871.67,410.52 1871.67,628.33 J4.13@1870,630 1870,756.46 1974.54,861 2272.77,861 2311,899.23 2311,915 2311,1503.09 2300,1514.09 2300,1745.78 2279,1766.78 2279,1771.78 2264.54,1786.25 2227.05,1786.25
  other v1: 1905,1770 1970,1770 2035,1770 2100,1770 2165,1770 2230,1770 1905,1810 1970,1810 2035,1810 2100,1810 2165,1810
A2_CELL6: C91.1 J4.12 J21.10 Q5.3 R96.1 R99.1 R128.1 R132.1 | length 1849.9
  Top Layer w10: J21.10@1770,519.29 J4.12@1770,630 R128.1@1770,729.13
  Bottom Layer w10: v1(1826,1510) 1845,1529 R132.1@1845,1715
  Bottom Layer w20: C91.1@1773.05,408.86 1771.53,410.39 1771.53,519.29 1771.53,628.47 J4.12@1770,630 1770,693.23 1965.77,889 2264,889 2285,910 2285,1375 2263.75,1396.25 2222.05,1396.25
  other v1: 1900,1380 1965,1380 2030,1380 2095,1380 2160,1380 2225,1380 1900,1420 1965,1420 2030,1420 2095,1420 2160,1420 2225,1420
A2_CELL7: C92.1 J4.11 J21.11 Q2.3 R23.1 R26.1 R110.1 R114.1 | length 1431.8
  Top Layer w10: J21.11@1670,519.29 J4.11@1670,630 R110.1@1670,730.07
  Bottom Layer w10: v1(1826,1105) 1845,1124 R114.1@1845,1308.5
  Bottom Layer w20: C92.1@1672.78,408.86 1671.39,410.25 1671.39,628.61 J4.11@1670,630 1955,915 2195,915 2217.05,937.05 2217.05,986.25
  Bottom Layer w40: Q2.3@2214.8,1061.57 2220.08,1061.57 2222.36,1059.28 2222.36,1007.64 v1(2225,1005)
  other v1: 1900,965 1965,965 2030,965 2095,965 2160,965 2225,965 1900,1005 1965,1005 2030,1005 2095,1005 2160,1005
A2_CELL8: C93.1 J4.10 J21.12 Q17.3 R15.1 R19.1 R93.1 R97.1 | length 1835
  Top Layer w10: J21.12@1570,519.29 J4.10@1570,630 R93.1@1570,731
  Bottom Layer w10: 1749,936 1771.5,913.5 R97.1@1845,913.5
  Bottom Layer w20: C93.1@1572.5,408.86 1571.25,410.11 1571.25,519.29 1571.25,628.75 J4.10@1570,630 1570,642.17 1584.18,656.35 1584.18,664.18 1749,829 1749,936 1749,1746 1703.75,1791.25 1662.05,1791.25
  other v1: 1330,1770 1395,1770 1460,1770 1525,1770 1590,1770 1655,1770 1330,1810 1395,1810 1460,1810 1525,1810 1590,1810 1655,1810
A2_CELL9: C94.1 J4.9 J21.13 Q15.3 R125.1 R126.1 R210.1 R214.1 | length 1607.2
  Top Layer w10: J21.13@1470,519.29 J4.9@1470,630 R210.1@1470,731.94
  Bottom Layer w10: v1(1240,1510) 1240,1595 1280,1635 R214.1@1280,1713.5
  Bottom Layer w20: C94.1@1472.22,408.86 1471.11,409.97 1471.11,519.29 1471.11,628.89 J4.9@1470,630 1710,870 1710,1226.72 1715,1231.72 1715,1395.22 1698.28,1411.94 1636.19,1411.94
  other v1: 1330,1375 1395,1375 1460,1375 1525,1375 1590,1375 1655,1375 1330,1415 1395,1415 1460,1415 1525,1415 1590,1415 1655,1415
A2_CELL10: C95.1 J4.8 J21.14 Q13.3 R119.1 R120.1 R194.1 R198.1 | length 1117.3
  Top Layer w10: J21.14@1370,519.29 J4.8@1370,630 R194.1@1370,732.88
  Bottom Layer w10: v1(1235,1110) 1235,1205 1275,1245 R198.1@1275,1298.5
  Bottom Layer w20: C95.1@1371.94,408.86 1370.97,409.83 1370.97,519.29 1370.97,629.03 J4.8@1370,630 1660,920 1660,968.3 1647.05,981.25
  other v1: 1330,975 1395,975 1460,975 1525,975 1590,975 1655,975 1330,1015 1395,1015 1460,1015 1525,1015 1590,1015 1655,1015
A2_CELL11: C96.1 J4.7 J21.15 Q11.3 R113.1 R116.1 R177.1 R181.1 | length 1796.3
  Top Layer w10: J21.15@1270,519.29 J4.7@1270,630 R177.1@1270,733.19
  Bottom Layer w10: 1195,913.5 R181.1@1275,913.5 1295,913.5
  Bottom Layer w20: v1(1080,1765) 1160,1765 1177.5,1747.5 1177.5,1372.5 1195,1355 1195,913.5 1195,713.36 1270,638.36 J4.7@1270,630 1270.83,629.17 1270.83,519.29 1270.83,409.69 C96.1@1271.67,408.86
  other v1: 755,1765 820,1765 885,1765 950,1765 1015,1765 755,1800 820,1800 885,1800 950,1800 1015,1800 1080,1800
A2_CELL12: C97.1 J4.6 J21.16 Q9.3 R105.1 R108.1 R161.1 R165.1 | length 1449.2
  Top Layer w10: J21.16@1170,519.29 J4.6@1170,630 R161.1@1170,732.25
  Bottom Layer w10: v1@667.05,1506.25 667.05,1572.05 700,1605 R165.1@700,1695
  Bottom Layer w20: 1072.05,1371.25 1123.75,1371.25 1169,1326 1169,702.59 1170,701.59 J4.6@1170,630 1170.69,629.31 1170.69,519.29 1170.69,409.55 C97.1@1171.39,408.86
  other v1: 755,1360 820,1360 885,1360 950,1360 1015,1360 1080,1360 755,1400 820,1400 885,1400 950,1400 1015,1400 1080,1400 660,1506.25
A2_CELL13: C98.1 J4.5 J21.17 Q7.3 R100.1 R101.1 R145.1 R149.1 | length 1005.2
  Top Layer w10: J21.17@1070,519.29 J4.5@1070,630 R145.1@1070,731.32
  Bottom Layer w10: v1@667.05,1101.25 667.05,1202.05 700,1235 R149.1@700,1295
  Bottom Layer w20: C98.1@1071.11,408.86 1070.56,409.41 1070.56,519.29 1070.56,629.44 J4.5@1070,630 1070,984.19 1077.05,991.25
  other v1: 755,965 820,965 885,965 950,965 1015,965 1080,965 755,1005 820,1005 885,1005 950,1005 1015,1005 1080,1005 660,1101.25
A2_CELL14: C99.1 J4.4 J21.18 Q4.3 R28.1 R67.1 R129.1 R133.1 | length 2473.9
  Top Layer w10: J21.18@970,519.29 J4.4@970,630 R129.1@970,730.38
  Bottom Layer w10: 613.1,913.5 R133.1@685,913.5
  Bottom Layer w20: v1(555,2300) 595,2300 607,2288 607,943.5 607,815.25 660.02,762.24 837.76,762.24 J4.4@970,630 970.42,629.58 970.42,519.29 970.42,409.27 C99.1@970.83,408.86
  other v1: 295,2170 360,2170 425,2170 490,2170 555,2170 295,2240 360,2240 425,2240 490,2240 555,2240 295,2300 360,2300 425,2300 490,2300
A2_CELL15: C100.1 J4.3 J21.19 Q3.3 R22.1 R27.1 R111.1 R115.1 | length 2187.7
  Top Layer w10: J21.19@870,519.29 J4.3@870,630 R111.1@870,729.44
  Bottom Layer w10: v1(188.09,1666.91) 186.99,1668.01 186.99,1691.91 181.99,1696.91 181.99,1822.79 211,1851.81 211,2047.16 207.95,2050.22 R115.1@207.95,2225.76
  Bottom Layer w20: v1@551.56,1603.44 580,1575 580,790 640,730 770,730 J4.3@870,630 870.28,629.72 870.28,519.29 870.28,409.14 C100.1@870.56,408.86
  other v1: 270,1450 335,1450 400,1450 465,1450 530,1450 270,1500 335,1500 400,1500 465,1500 530,1500 270,1570 335,1570 400,1570 465,1570 530,1570 555,1600 270,1630 335,1630 400,1630 465,1630 530,1630
A2_CELL16S: C101.1 J4.2 J21.20 R18.1 R21.1 R94.1 R98.1 | length 1483.2
  Top Layer w10: J21.20@770,519.29 J4.2@770,630 R94.1@770,728.5
  Bottom Layer w10: v1(185,865) 185,972.2 177.95,979.26 177.95,1083.75 211,1116.81 211,1504.21 R98.1@207.95,1507.26
  Bottom Layer w20: v1(545,865) 545,745 595,695 705,695 J4.2@770,630 J21.20@770,519.29 770.14,519.15 770.14,409 C101.1@770.28,408.86
  other v1: 265,710 330,710 395,710 460,710 525,710 265,760 330,760 395,760 460,760 265,830 330,830 395,830 460,830 525,830 265,890 330,890 395,890 460,890 525,890
A2_CELL_TOP: C102.1 D44.1 J4.1 J21.21 R192.2 | length 1116.4
  Top Layer w30: J21.21@669.29,519.29 J21.21@670,519.29
  Top Layer w50: R192.2@355,435 585,435 J21.21@669.29,519.29 ; J21.21@670,519.29 J4.1@670,630
  Bottom Layer w20: v1(538.54,445) 540,443.54 540,426.77 ; C102.1@670,408.86 J21.21@670,519.29 J4.1@670,630 ; D44.1@748.82,202.99 775,176.81 D44.1@775,165
  Bottom Layer w50: 540,426.77 540,315 652.01,202.99 D44.1@748.82,202.99
  other v1: 538.83,410.09
A2_COMHN: C50.1 J28.2 R86.1 R90.1 U4.42 | length 811.9
  Top Layer w10: U4.42@1558.82,2745.12 1601.82,2745.12 1602.93,2744 1996.63,2744 2007.63,2755 2060,2755 J28.2@2170.39,2755 ; J28.2@2165,2745 2172.7,2752.7 2210,2790 2275,2790 R90.1@2341.69,2790
A2_COMHP: C51.1 J28.3 R82.1 R86.2 U4.43 | length 843.4
  Top Layer w10: U4.43@1558.82,2764.8 1604.76,2764.8 1609.56,2760 1990,2760 2044.74,2814.74 C51.1@2049,2819 ; C51.1@2047.24,2812.24 2051.5,2816.5 2054.74,2819.74 C51.1@2056.5,2821.5 ; C51.1@2050,2808.5 2128.5,2808.5 J28.3@2165,2845 2275,2845 2333.5,2845 R82.1@2343.5,2855 ; R86.2@2275,2851.5 R86.2@2275,2852.48
A2_COMLN: C43.1 J27.1 R73.1 R75.2 U4.41 | length 1557.3
  Top Layer w10: U4.41@1558.82,2725.43 1917.19,2725.43 1940,2702.63 1940,2665 ; C43.1@1975,2661.5 1971.5,2665 1940,2665 ; R75.2@2801.85,2563.7 2798.35,2560.2 R73.1@2733.35,2560.2 2680.2,2560.2 2622.5,2502.5 2576,2456 1979,2456 1940,2495 1940,2665
A2_COMLP: C42.1 J27.2 R69.2 R73.2 U4.40 | length 1571.6
  Top Layer w10: U4.40@1558.82,2705.75 1914.25,2705.75 1924,2696 1924,2665 ; C42.1@1885,2666.5 1922.5,2666.5 1924,2665 ; R69.2@2801.85,2493.7 2736.85,2493.7 R73.2@2733.35,2497.2 2702.2,2497.2 J27.2@2615,2410 2607.85,2410 2577.85,2440 1960,2440 1924,2476 1924,2665
A2_COMMH_N_OPT: R91.2 T2.6 | length 129.4
  Top Layer w10: R91.2@2542.99,2720 2613.76,2720 2643.76,2750 T2.6@2660,2750
A2_COMMH_P_OPT: R83.2 T2.4 | length 130.9
  Top Layer w10: R83.2@2541.5,2920 2613.76,2920 2643.76,2950 T2.4@2660,2950
A2_COMML_N_OPT: C41.1 R76.1 | length 63.8
  Top Layer w10: R76.1@3159.84,2563.7 3221.77,2563.7 C41.1@3223.07,2565
A2_COMML_P_OPT: C40.1 R70.1 | length 65.7
  Top Layer w10: R70.1@3156.5,2490 3208.07,2490 C40.1@3218.07,2480
A2_CVDD: C8.1 C17.1 C39.2 C152.1 J1.1 R153.2 U3.1 U4.45 | length 3803.7
  Top Layer w8: R153.2@1691.5,3025 1692.64,3023.85 1879.05,3023.85 1882.6,3027.4 U3.1@1882.6,3108.82
  Top Layer w10: U4.45@1558.82,2804.17 1559.72,2805.08 1594.64,2805.08 1610.74,2821.18 1685.01,2821.18 1693.83,2830 1769.13,2830 ; 1769.13,2828.62 1785.5,2845 1810,2845 1870,2845 C17.1@1917.12,2845 ; C39.2@1810,2846.38 1870,2846.38 1917.12,2846.38 1938.5,2825 C17.1@1945,2825 ; C17.1@1948,2820 1968,2840 2005.15,2840 v2(2005.42,2840.28)
  Bottom Layer w8: v2@1823.85,3023.85 v2@1827,3023.85
  Bottom Layer w10: J1.1@270,3650 315,3695 640,3695 725,3780 1979.14,3780 2035,3724.14 2035,3380.87 2029.5,3375.37 2029.5,3023.85 ; v2@1827,3023.85 2029.5,3023.85 ; v2(2005.42,2840.28) 2029.5,2864.35 2029.5,3023.85
  other v2: 1827,3025
A2_CVDD_SW: C12.2 C20.1 C21.1 U3.6 U5.16 U7.16 U8.16 | length 1939.3
  Top Layer w8: v2(1035,3300) 1035,3281.04 1039.86,3276.18 U7.16@1054.35,3276.18 ; C12.2@1176.38,3055 1176.38,3100.94 1180.87,3105.43 U5.16@1182.86,3105.43 1183.14,3105.72 1234.71,3105.72 v2(1235,3106) ; U3.6@1880.25,3223.38 1882.6,3221.02 U3.6@1882.6,3211.18
  Top Layer w10: v2(1695,3275) 1695.22,3274.78 1753.96,3274.78 U8.16@1754.17,3274.57 ; v2(1855,3265) 1856.86,3263.14 1856.86,3239 1860.86,3235 1875.79,3235 1882.6,3228.19 U3.6@1882.6,3225.73
  Bottom Layer w8: v2(1035,3300) C20.1@1035,3275 1110.4,3275 1125.11,3289.71 1376.48,3289.71 1390.48,3275.71 1641.85,3275.71 C21.1@1685,3232.56 ; v2(1235,3106) 1345.87,3106 1347.88,3104 1410.68,3104 1411.69,3105.01 1613.72,3105.01 1614.22,3104.51 1785,3104.51 1855,3174.51 v2(1855,3265)
  Bottom Layer w10: C21.1@1685,3228.62 1685,3232.56 1685,3261.75 1695,3271.75 v2(1695,3275) 1824,3275 1831.7,3267.3 1852.7,3267.3 v2(1855,3265)
A2_DVDD: C18.2 U4.49 | length 57.9
  Top Layer w10: U4.49@1482.05,2940 1482.05,2940.39 1482.95,2941.3 1519.8,2941.3 C18.2@1533.5,2955
A2_EE_NCS: U5.14
A2_EE_SCK: U5.2
A2_EE_SI: U5.5
A2_EE_SO: U5.11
